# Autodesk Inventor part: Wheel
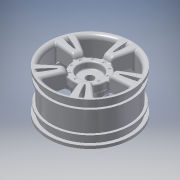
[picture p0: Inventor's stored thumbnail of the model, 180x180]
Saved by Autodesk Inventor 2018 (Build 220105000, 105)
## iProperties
Shininess: 54.0
Length Units: 11272
Angle Units: 11279
Time Units: 11290
Mass Units: 11286
Length Display Precision: 4
Angle Display Precision: 2
Compacted: True
Company: Autodesk
Created: 2000-05
Part Number: Wheel
Project: Inventor Samples
User Status: IN PROGRESS
Document SubType Name: Modeling
Designer: Autodesk, Inc.
Density: 2.71 g/cm^3
Material: Aluminum-6061
Mass: 26.0183 g
Surface Area: 145.445 cm^2
Volume: 9.60086 cm^3
Appearance: Light Grey
Density: 0.0
Volumn: 0.0
Area: 0.0
PropertySet Name: Model Information
Control State: 0
Master: False
Checked Out: False
Author: Autodesk, Inc.
Revision Number: A
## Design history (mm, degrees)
node "Revolution1" dims "d2" = 90 deg
  sketch "Sketch2"
    geometry: L1 (-26.543, 0)-(0, 0); L2 (0, 0)-(0, 25.971); L3 (0, 25.971)-(-26.543, 25.971); L4 (-26.543, 0)-(-26.543, 25.971); L5 (-31.852, 0)-(5.309, 0) reference; 1 further point
    constraints: 8 end point, 2 parallel, 1 collinear, 1 horizontal, 1 perpendicular, 1 point on line
    dimensions: "d0" = 51.943 diameter of L3 L1; "d1" = 26.543 distance between parallel lines of L4 L2
node "Revolution2" dims "d6" = 90 deg
  sketch "Sketch3"
    geometry: L1 (-31.852, 0)-(5.309, 0) reference; L2 (0, -25.971)-(0, 25.971) reference; L3 (-26.543, 25.971)-(0, 25.971) reference; L4 (-1.778, 25.971)-(-1.778, 23.94); L5 (-1.778, 23.94)-(-24.765, 23.94); L6 (-24.765, 23.94)-(-24.765, 25.971); L7 (-26.543, -25.971)-(-26.543, 25.971) reference
    constraints: 6 end point, 2 perpendicular, 2 point on line, 1 parallel
    dimensions: "d3" = 47.879 diameter of L5 L1; "d4" = 1.778 distance between parallel lines of L2 L4; "d5" = 1.778 distance between parallel lines of L6 L7 (= d4)
node "Revolution3" dims "d12" = 90 deg
  sketch "Sketch4"
    geometry: L1 (-24.765, 23.94)-(-1.778, 23.94) reference; L2 (0, -25.971)-(0, 25.971) reference; L3 (-26.543, -25.971)-(-26.543, 25.971) reference; L4 (-31.852, 0)-(5.309, 0) reference; L5 (-20.701, 23.94)-(-20.701, 25.4); L6 (-20.701, 25.4)-(-19.558, 25.4); L7 (-19.558, 25.4)-(-19.558, 23.94); L8 (-6.985, 23.94)-(-6.985, 25.4); L9 (-6.985, 25.4)-(-5.842, 25.4); L10 (-5.842, 25.4)-(-5.842, 23.94)
    constraints: 12 end point, 4 perpendicular, 4 point on line, 2 parallel, 1 collinear
    dimensions: "d7" = 1.143 distance between parallel lines of L7 L5 (= d8); "d8" = 1.143 distance between parallel lines of L10 L8; "d9" = 6.985 distance between parallel lines of L2 L8; "d10" = 6.985 distance between parallel lines of L3 L7; "d11" = 50.8 diameter of L9.end L4
node "Extrusion1" dims "d14" = 11.811, "d15" = 0
  sketch "Sketch5"
    geometry: C1 r 25.971 at (0, 0) reference; C2 r 22.86 at (0, 0)
    constraints: 1 centre point, 1 coincident
    dimensions: "d13" = 45.72 diameter of C2
node "Extrusion2" dims "d17" = 11.811, "d18" = 0
  sketch "Sketch6"
    geometry: C1 r 22.86 at (0, 0) reference; C2 r 8.382 at (0, 0)
    constraints: 1 centre point, 1 coincident
    dimensions: "d16" = 16.764 diameter of C2
node "Extrusion3" dims "d19" = 6.731, "d20" = 0
  sketch "Sketch7"
    geometry: C1 r 8.382 at (0, 0) reference
node "Fillet4" dims "d40" = 2.54
node "Extrusion5" dims "d46" = 8.89 (computed from d19), "d47" = 0
  sketch "Sketch10"
    geometry: L1 (0, 0)-(0, 25.971); L2 (-6.072, 24.664)-(-2.989, 11.822); L3 (6.072, 24.664)-(2.989, 11.822); A1 r 25.4 centre (0, 0) between (1.27, 25.368) and (-1.27, 25.368) reference; A2 r 57.15 centre (-55.876, 24.699) between (0, 12.7) and (1.27, 25.368); A3 r 57.15 centre (55.876, 24.699) between (-1.27, 25.368) and (0, 12.7); A4 r 8.382 centre (0, 0) between (-4.859, 6.83) and (4.859, 6.83) reference; A5 r 4.763 centre (-7.62, 10.71) between (-4.859, 6.83) and (-2.989, 11.822); A6 r 4.763 centre (7.62, 10.71) between (2.989, 11.822) and (4.859, 6.83); 1 further point
    constraints: 14 point on circle, 6 end point, 4 centre point, 4 tangent, 3 horizontal alignment, 2 equal radius, 1 point on line, 1 vertical, 1 vertical alignment, 1 other
    dimensions: "d41" = 12.7 distance of A2.start point (0, 0); "d42" = 2.54 distance of A1.start A1.end; "d43" = 57.15 radius of A2; "d44" = 27 deg angle of L3 L2; "d45" = 4.7625 radius of A5; "d51" = 15.24 distance of A6.centre A5.centre
node "Fillet6" dims "d59" = 0.39687
node "Circular Pattern2" dims "d48" = 50 (= Spokes), "d50" = 360 deg
node "Revolution5" dims "d53" = 90 deg
  sketch "Sketch11"
    geometry: L1 (-24.765, 23.906)-(-20.701, 23.906) reference; L2 (-19.558, 23.94)-(-6.985, 23.94) reference; L3 (-20.701, 25.4)-(-19.558, 25.4) reference; L4 (-26.543, 25.971)-(-24.765, 25.971) reference; L5 (-26.543, 25.971)-(-26.543, 27.241); L6 (-26.543, 27.241)-(-6.985, 27.242); L7 (-6.985, 27.242)-(-6.985, 23.94); L8 (-19.558, 25.4)-(-19.558, 23.94); L9 (-20.701, 25.4)-(-20.701, 23.906); L10 (-24.765, 25.971)-(-24.765, 23.906); L11 (-30.455, 0)-(-3.073, 0) reference
    constraints: 12 end point, 4 parallel, 2 perpendicular
    dimensions: "d52" = 1.27 distance of L4.start L5.end
node "Revolution6" dims "d57" = 90 deg
  sketch "Sketch12"
    geometry: L1 (-26.543, -25.971)-(-26.543, 25.971) reference; L2 (-19.812, 8.382)-(-26.543, 8.382) reference; L3 (-28.689, 0)-(-17.974, 0) reference; L4 (-19.812, 0)-(-19.812, 8.382); L5 (-23.645, 10.172)-(-21.261, 9.963); A1 r 3.175 centre (-23.368, 13.335) between (-26.543, 13.335) and (-23.645, 10.172); A2 r 1.587 centre (-21.399, 8.382) between (-19.812, 8.382) and (-21.261, 9.963)
    constraints: 4 end point, 4 point on circle, 4 tangent, 2 centre point, 2 point on line, 1 perpendicular
    dimensions: "d54" = 3.175 radius of A1; "d55" = 1.5875 radius of A2; "d56" = 85 deg angle of L4 L5
node "Fillet5" dims "d58" = 5.08
workaxis "Work Axis2"
workplane "Work Plane3"
  workpoint "Work Point3"
  workpoint "Work Point4"
  workpoint "Work Point5"
node "Revolution8" dims "d97" = 90 deg
  sketch "Sketch17"
    geometry: L1 (-1.449, 9.963)-(-3.833, 10.172) reference; L2 (0, 6.732)-(-3.833, 7.067); L3 (25.121, 0)-(-12.045, 0) reference; L4 (-3.833, 7.067)-(-3.833, 10.641); L5 (-3.833, 10.641)-(1.27, 10.641); L6 (1.27, 10.641)-(1.27, 6.732); L7 (1.27, 6.732)-(0, 6.732); L8 (0, -2.511)-(0, 6.732) reference; A1 r 1.587 centre (-1.588, 8.382) between (0, 8.382) and (-1.449, 9.963) reference
    constraints: 10 end point, 3 parallel, 2 perpendicular
    dimensions: "d93" = 1.27 distance between parallel lines of L6 L8
node "Fillet14" dims "d100" = 1.5875
node "Fillet15" dims "d101" = 1.5875
node "Fillet16" dims "d102" = 0.8128
node "Fillet17" dims "d103" = 0.8128
node "Fillet18" dims "d104" = 0.8128
node "Extrusion7" dims "d71" = 5.08, "d72" = 0
  sketch "Sketch14"
    geometry: L1 (-6.032, 3.483)-(-6.032, -3.483); L2 (-6.032, -3.483)-(0, -6.966); L3 (0, -6.966)-(6.032, -3.483); L4 (6.032, -3.483)-(6.032, 3.483); L5 (6.032, 3.483)-(0, 6.966); L6 (0, 6.966)-(-6.032, 3.483); C1 r 8.382 at (0, 0) reference; C2 r 6.032 at (0, 0)
    constraints: 12 end point, 6 tangent, 4 equal length, 2 vertical, 1 centre point, 1 coincident
    dimensions: "d70" = 12.065 distance between parallel lines of L4 L1
node "Fillet9" dims "d73" = 3.175
node "Extrusion8" dims "d79" = 25.4, "d80" = 0
  sketch "Sketch15"
    geometry: L1 (-3.285, 13.055)-(-4.738, 19.106) reference; L2 (-2.989, 11.822)-(-3.285, 13.055) reference; L3 (4.738, 19.106)-(3.285, 13.055) reference; L4 (2.989, 11.822)-(3.285, 13.055) reference; L5 (0, 0)-(-4.166, 22.477); L6 (0, 0)-(4.166, 22.477); L7 (-2.911, 22.674)-(-1.198, 13.431); L8 (1.198, 13.431)-(2.911, 22.674); L9 (0, 0)-(0, 13.652); C1 r 25.971 at (0, 0) reference; A1 r 22.86 centre (0, 0) between (-4.166, 22.477) and (4.166, 22.477) reference; A2 r 57.15 centre (55.876, 24.699) between (-1.051, 19.657) and (-0.391, 14.691) reference; A3 r 57.15 centre (-55.876, 24.699) between (0.391, 14.691) and (1.051, 19.657) reference; A4 r 1.218 centre (0, 13.652) between (-1.198, 13.431) and (1.198, 13.431); A5 r 2.488 centre (0, 13.652) between (-2.446, 13.199) and (2.446, 13.199); 4 further points
    constraints: 10 end point, 8 point on circle, 2 centre point, 2 parallel, 2 point on line, 2 tangent, 1 concentric, 1 vertical
    dimensions: "d74" = 1.27 distance between parallel lines of L7 L5; "d75" = 1.27 distance between parallel lines of L6 L8 (= d74); "d76" = 13.6525 distance of A1.centre L9.end; "d77" = 21 deg angle of L8 L7; "d78" = 1.27 radial gap between concentric circles of A4 A5 (= d75)
node "Circular Pattern3" dims "d81" = 50 (= Spokes), "d83" = 360 deg
node "Extrusion6" dims "d68" = 2.159, "d69" = 0
  sketch "Sketch13"
    geometry: C1 r 2.381 at (0, 0); C2 r 23.94 at (0, 0) reference
    constraints: 1 centre point, 1 concentric
    dimensions: "d67" = 4.7625 diameter of C1
workplane "Work Plane4"
node "Extrusion9" dims "d108" = 25.4, "d109" = 20 deg
  sketch "Sketch18" dims "d106" = 17.78
    geometry: L1 (0, 36.36)-(0, -36.36) reference; C1 r 2.381 at (0, 0) reference; C2 r 0.635 at (0, 8.89); 1 further point
    constraints: 1 centre point, 1 coincident, 1 point on line, 1 vertical alignment, 2 other
    dimensions: "d107" = 1.27 diameter of C2
node "Fillet19" dims "d110" = 0.127
node "Circular Pattern4" dims "d111" = 100, "d113" = 360 deg
node "Fillet20" dims "d114" = 0.8128
node "Fillet21" dims "d115" = 0.8128
node "Fillet22" dims "d116" = 0.8128
body "Solid1"
other parameters: "d95" = 5 deg (derived), "d96" = 22.88399 (derived), "d105" = -0.381
